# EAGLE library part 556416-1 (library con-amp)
AMP connector
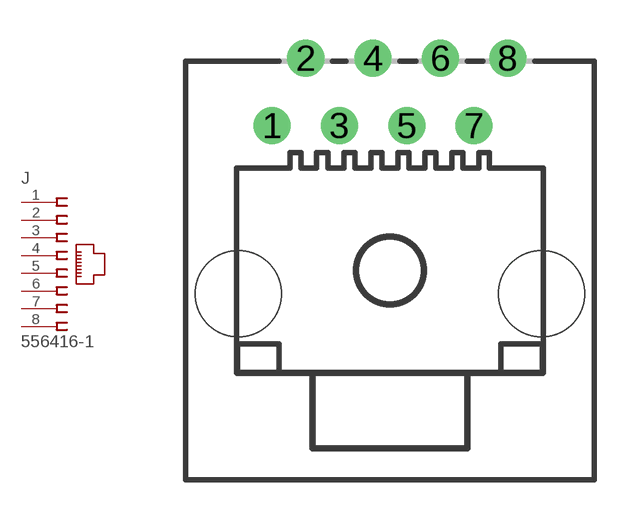
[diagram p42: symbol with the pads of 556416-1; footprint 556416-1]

Designator prefix J

## 556416-1 (MF: TYCO ELECTRONICS; MPN: 5556416-1; OC_FARNELL: 1087508; OC_NEWARK: 42K7302)  [556416-1]
1  1  pas
2  2  pas
3  3  pas
4  4  pas
5  5  pas
6  6  pas
7  7  pas
8  8  pas

## Footprint 556416-1 (pad centres in mm)
Modular Jack without Panel Stops
drill 0.889 round: 1 -4.445,5.461; 2 -3.175,8.001; 3 -1.905,5.461; 4 -0.635,8.001; 5 0.635,5.461; 6 1.905,8.001; 7 3.175,5.461; 8 4.445,8.001
hole 3.251 at -5.715,-0.889
hole 3.251 at 5.715,-0.889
